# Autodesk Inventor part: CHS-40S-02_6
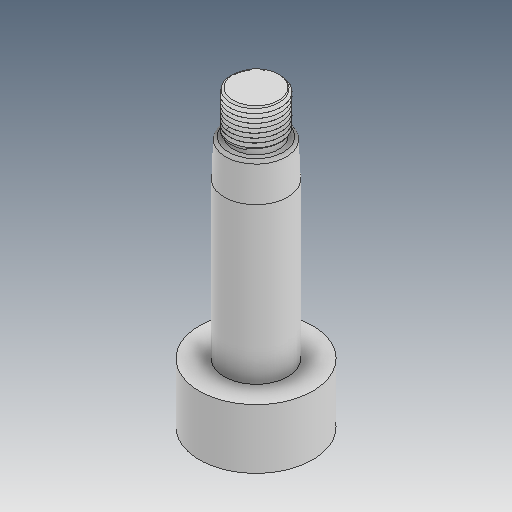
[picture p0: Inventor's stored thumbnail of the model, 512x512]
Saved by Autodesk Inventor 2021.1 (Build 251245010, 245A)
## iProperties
Created: 2019-04
Part Number: CHS-40S-02_6
Material: Ogólny
Document SubType Name: Modeling
Designer: user
Density: 1 g/cm^3
Appearance: Domyślna
Author: user
Revision Number: ÈÎºÎ
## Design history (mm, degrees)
feature "ÊäÈë1"
feature "ÊäÈë2"
node "Bryła1"
node "Bryła2"
